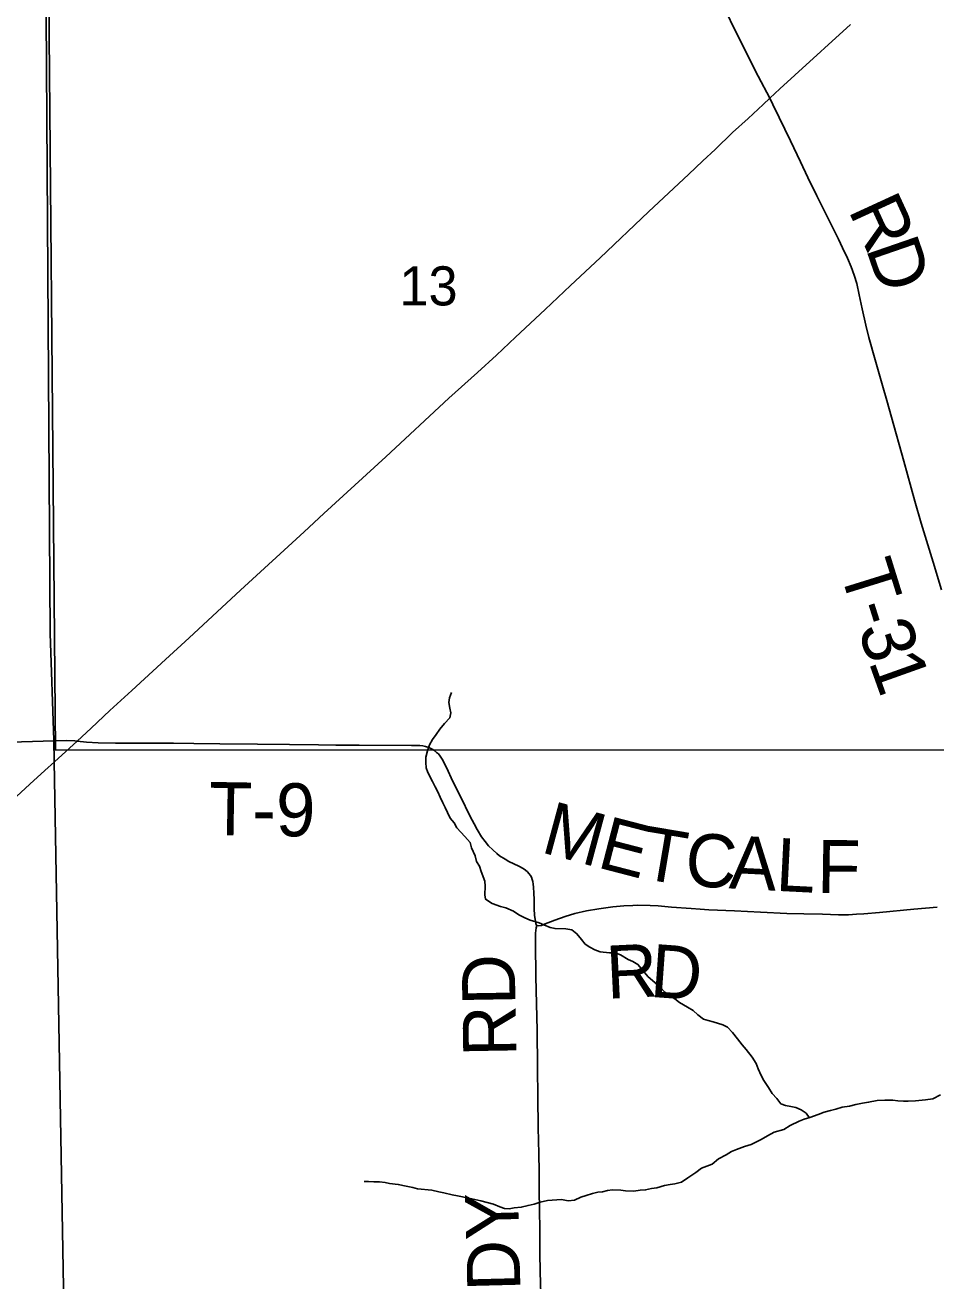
# Model space of a CAD drawing. Extents: x 0 to 34, y 0 to 22.
# Drawn here: x 2.612 to 3.587, y 14.792 to 16.137 of the extents above; entities that cross this region are included whole.
import ezdxf

# ---------------------------------------------------------------- set-up
doc = ezdxf.new("R2010")
doc.units = 0
for name, color, linetype in [('Default', 7, 'Continuous'), ('GM_X_Minor_River', 7, 'Continuous'), ('GM_X_Section', 7, 'Continuous'), ('GM_X_Section_Text', 7, 'Continuous'), ('GM_X_State_Route', 7, 'Continuous'), ('GM_X_Township_Road', 7, 'Continuous'), ('GM_X_Township_Road_Text', 7, 'Continuous'), ('SH_Cut_Line', 7, 'Continuous')]:
    doc.layers.add(name, color=color, linetype=linetype)

msp = doc.modelspace()

# ---------------------------------------------------------------- linework, layer by layer
at = {"layer": 'Default'}
msp.add_lwpolyline([(2.1, 18.375), (2.1, 14.3539), (2.1651, 14.3567), (2.6607, 14.3625), (2.6434, 15.3487), (2.6428, 15.3713), (2.6388, 15.4856), (2.6332, 16.3685), (2.6231, 17.3771), (2.6129, 17.8818), (2.6122, 18.05), (2.6118, 18.3803)], close=True, dxfattribs=at)
msp.add_lwpolyline([(2.6231, 17.3771), (2.6332, 16.3685), (2.6388, 15.4856), (2.6428, 15.3713), (2.6434, 15.3487), (2.6607, 14.3625), (2.7339, 14.3605), (3.1736, 14.3499), (3.5171, 14.3547), (3.6708, 14.3479), (4.282, 14.3483), (4.5209, 14.3512)], dxfattribs=at)
at = {"layer": 'GM_X_Minor_River'}
for points in [[(3.4517, 14.9671), (3.4484, 14.9718), (3.443, 14.9756), (3.4373, 14.9779), (3.4319, 14.979), (3.4262, 14.9801), (3.4213, 14.982), (3.417, 14.9874), (3.4121, 14.9931), (3.4079, 14.9995), (3.4029, 15.0068), (3.4002, 15.0121), (3.3971, 15.0193), (3.3948, 15.025), (3.3906, 15.0319), (3.3841, 15.0399), (3.3799, 15.0452), (3.3749, 15.0513), (3.3696, 15.0581), (3.3642, 15.0638), (3.3592, 15.0665), (3.3489, 15.0695), (3.3436, 15.0711), (3.3386, 15.0726), (3.3325, 15.0772), (3.3275, 15.0817), (3.3214, 15.0855), (3.3126, 15.0905), (3.3076, 15.0943), (3.3019, 15.0977), (3.2969, 15.1015), (3.292, 15.1068), (3.2866, 15.1114), (3.279, 15.1182), (3.274, 15.1243), (3.2683, 15.1312), (3.2629, 15.1342), (3.2579, 15.1365), (3.2495, 15.1415), (3.2438, 15.1434), (3.2377, 15.1437), (3.2278, 15.1445), (3.222, 15.1468), (3.2167, 15.1495), (3.2117, 15.1529), (3.2079, 15.1578), (3.2029, 15.1639), (3.1976, 15.1681), (3.1911, 15.1692), (3.1796, 15.1696), (3.1743, 15.1708), (3.1674, 15.1734), (3.1624, 15.1757), (3.1529, 15.1784), (3.1472, 15.1811), (3.1407, 15.1841), (3.1349, 15.1883), (3.1269, 15.1917), (3.1212, 15.1932), (3.112, 15.1963), (3.1051, 15.2009), (3.1044, 15.2058), (3.1047, 15.2149), (3.1043, 15.2202), (3.1005, 15.2305), (3.0986, 15.2362), (3.0955, 15.2412), (3.094, 15.2476), (3.0901, 15.256), (3.0886, 15.2617), (3.0829, 15.2682), (3.0744, 15.2773), (3.0714, 15.2826), (3.0672, 15.2876), (3.0645, 15.2937), (3.0618, 15.299), (3.0595, 15.3043), (3.0564, 15.3104), (3.0541, 15.3161), (3.0511, 15.3214), (3.0484, 15.3271), (3.0434, 15.3366), (3.0415, 15.3416), (3.0411, 15.3473), (3.0411, 15.353), (3.0429, 15.3598), (3.0452, 15.3663), (3.0483, 15.372), (3.0521, 15.3773), (3.0563, 15.383), (3.0612, 15.3891), (3.0669, 15.3952), (3.068, 15.4005), (3.0669, 15.4054), (3.0657, 15.4115), (3.0665, 15.4165), (3.0688, 15.4222)], [(3.5922, 14.9915), (3.5838, 14.9873), (3.5762, 14.9861), (3.5655, 14.985), (3.5575, 14.9846), (3.5525, 14.9846), (3.5464, 14.985), (3.5411, 14.9858), (3.5327, 14.9858), (3.5243, 14.9854), (3.5151, 14.9835), (3.5086, 14.9824), (3.5014, 14.9812), (3.4949, 14.9793), (3.4869, 14.9782), (3.48, 14.9763), (3.4743, 14.9748), (3.4678, 14.9729), (3.4613, 14.9706), (3.4522, 14.9672), (3.4461, 14.9653)], [(3.4461, 14.9653), (3.4408, 14.9634), (3.4312, 14.9585), (3.4244, 14.9543), (3.4141, 14.9516), (3.4068, 14.9475), (3.4, 14.9437), (3.3893, 14.9383), (3.3824, 14.9361), (3.3737, 14.933), (3.3683, 14.9307), (3.3626, 14.9273), (3.3546, 14.9228), (3.3477, 14.9171), (3.3363, 14.9129), (3.3302, 14.9083), (3.3215, 14.9026), (3.315, 14.8981), (3.3077, 14.8962), (3.3028, 14.8954), (3.2967, 14.8943), (3.2883, 14.892), (3.2829, 14.8912), (3.2765, 14.8897), (3.2707, 14.8893), (3.2639, 14.8882), (3.2551, 14.8886), (3.2501, 14.8894), (3.241, 14.8897), (3.2356, 14.889), (3.2303, 14.8878), (3.2253, 14.8871), (3.2196, 14.886), (3.2127, 14.8837), (3.207, 14.8818), (3.2002, 14.8787), (3.1937, 14.878), (3.1864, 14.8795), (3.1715, 14.8784), (3.1635, 14.8765), (3.157, 14.8746), (3.1506, 14.8731), (3.1433, 14.8712), (3.1357, 14.8704), (3.1303, 14.8696), (3.1254, 14.8697), (3.1204, 14.8716), (3.1135, 14.8746), (3.1002, 14.878), (3.0872, 14.8807), (3.075, 14.8834), (3.0692, 14.8845), (3.0605, 14.8864), (3.0551, 14.8876), (3.0475, 14.8895), (3.0322, 14.891), (3.0272, 14.8921), (3.02, 14.8937), (3.0116, 14.8956), (3.0024, 14.8967), (2.9975, 14.8975), (2.9914, 14.8982), (2.9856, 14.8982), (2.9799, 14.8986), (2.975, 14.8986)]]:
    msp.add_lwpolyline(points, dxfattribs=at)
at = {"layer": 'GM_X_Section'}
msp.add_lwpolyline([(2.6357, 16.367), (3.1951, 16.3831), (3.3278, 16.3702), (3.6522, 16.3668), (3.6534, 16.349), (3.6643, 15.3607), (2.6446, 15.3609)], close=True, dxfattribs=at)
at = {"layer": 'GM_X_State_Route'}
for points in [[(2.6436, 15.3481), (2.6677, 15.3702), (2.6828, 15.3841), (2.7029, 15.4031), (2.7263, 15.4244), (2.7626, 15.4578), (2.7879, 15.4809), (2.8428, 15.5319), (2.9108, 15.5944), (2.9319, 15.614), (2.9983, 15.6748), (3.0659, 15.7374), (3.0963, 15.7651), (3.1168, 15.7836), (3.1372, 15.8028), (3.1689, 15.8326), (3.196, 15.8581), (3.2278, 15.8878), (3.2797, 15.9369), (3.3067, 15.9625), (3.3225, 15.977), (3.3378, 15.9917), (3.3509, 16.0039), (3.3696, 16.0219), (3.3861, 16.0371), (3.4023, 16.0521), (3.4093, 16.0586), (3.4202, 16.0686), (3.4362, 16.0833), (3.4959, 16.1377)], [(2.1, 14.819), (2.1251, 14.8471), (2.1408, 14.8645), (2.1583, 14.8839), (2.179, 14.907), (2.1997, 14.9302), (2.2353, 14.9691), (2.2482, 14.9825), (2.2682, 15.002), (2.291, 15.023), (2.3069, 15.0378), (2.3275, 15.0567), (2.4005, 15.124), (2.4301, 15.1514), (2.5189, 15.2336), (2.5599, 15.2716), (2.617, 15.3242), (2.6331, 15.3388), (2.6436, 15.3481)]]:
    msp.add_lwpolyline(points, dxfattribs=at)
at = {"layer": 'GM_X_Township_Road'}
for points in [[(3.4093, 16.0586), (3.3971, 16.0824), (3.3803, 16.1156), (3.354, 16.1685), (3.3365, 16.2049), (3.3195, 16.2415), (3.3069, 16.2699), (3.2898, 16.3099), (3.2723, 16.3531), (3.2668, 16.3676), (3.264, 16.3765), (3.2633, 16.379)], [(3.5933, 15.5323), (3.5842, 15.562), (3.5714, 15.6035), (3.5648, 15.6272), (3.5528, 15.6702), (3.5396, 15.7171), (3.5347, 15.7351), (3.5301, 15.7509), (3.5224, 15.7786), (3.5155, 15.8025), (3.5121, 15.8156), (3.5084, 15.833), (3.5051, 15.8483), (3.5025, 15.8604), (3.4998, 15.8692), (3.4967, 15.8781), (3.4925, 15.8873), (3.4874, 15.8986), (3.4828, 15.9078), (3.4709, 15.932), (3.4599, 15.9543), (3.4503, 15.9738), (3.4423, 15.9906), (3.4315, 16.0129), (3.4195, 16.038), (3.4127, 16.052), (3.4093, 16.0586)], [(2.1, 15.3565), (2.1347, 15.3575), (2.1565, 15.3582), (2.1938, 15.359), (2.2405, 15.3602), (2.2809, 15.3614), (2.3182, 15.3623), (2.3586, 15.3633), (2.4177, 15.3648), (2.4581, 15.3659), (2.4891, 15.3664), (2.5202, 15.3673), (2.5482, 15.3682), (2.5855, 15.3689), (2.643, 15.3707)], [(2.643, 15.3707), (2.6563, 15.3709), (2.6655, 15.3705), (2.6677, 15.3702)], [(2.6677, 15.3702), (2.6778, 15.3692), (2.6902, 15.3683), (2.7089, 15.368), (2.7461, 15.3679), (2.771, 15.3679), (2.7927, 15.3677), (2.8207, 15.3673), (2.8611, 15.3669), (2.8953, 15.3667), (2.9263, 15.3662), (2.9449, 15.3661), (2.9698, 15.366), (3.0257, 15.3657), (3.0349, 15.3654), (3.0379, 15.3651), (3.0409, 15.3644), (3.0442, 15.3635), (3.0466, 15.3624), (3.0487, 15.3612), (3.0508, 15.3598), (3.0526, 15.3582), (3.0546, 15.3565), (3.0566, 15.354), (3.0587, 15.3509), (3.0633, 15.342), (3.0702, 15.327), (3.0782, 15.3108), (3.0886, 15.2895), (3.0928, 15.2816), (3.0961, 15.2756), (3.1009, 15.2679), (3.1045, 15.2629), (3.1083, 15.2582), (3.1128, 15.2538), (3.1171, 15.2499), (3.1201, 15.2476), (3.126, 15.2437), (3.1301, 15.2414), (3.1406, 15.2362), (3.1455, 15.2337), (3.148, 15.2319), (3.1499, 15.2303), (3.1516, 15.2284), (3.1531, 15.2264), (3.1542, 15.2244), (3.1551, 15.222), (3.1557, 15.2198), (3.1562, 15.2171), (3.1565, 15.2137), (3.1568, 15.2076), (3.157, 15.2005), (3.1572, 15.1912), (3.1576, 15.1835), (3.1584, 15.1773), (3.159, 15.1746), (3.1601, 15.1729)], [(3.1601, 15.1729), (3.1623, 15.1725), (3.165, 15.1729), (3.1673, 15.174), (3.1793, 15.1785), (3.1903, 15.1826), (3.2007, 15.1856), (3.2131, 15.1885), (3.2264, 15.1907), (3.2413, 15.1927), (3.2532, 15.1938), (3.2629, 15.1944), (3.268, 15.1946), (3.2815, 15.1943), (3.2899, 15.1938), (3.3043, 15.1926), (3.3254, 15.1909), (3.3347, 15.1903), (3.344, 15.1897), (3.3718, 15.1886), (3.3996, 15.1871), (3.4275, 15.1858), (3.4457, 15.1854), (3.466, 15.1848), (3.4829, 15.1843), (3.4891, 15.1843), (3.4936, 15.1844), (3.5023, 15.1848), (3.5101, 15.1854), (3.5267, 15.1868), (3.5638, 15.1902), (3.5885, 15.1925)], [(3.1642, 14.7779), (3.1637, 14.802), (3.1633, 14.8223), (3.1631, 14.8468), (3.1627, 14.8684), (3.1626, 14.8894), (3.1625, 14.9085), (3.1621, 14.9293), (3.1618, 14.9417), (3.1615, 14.9572), (3.1612, 14.9883), (3.1608, 15.021), (3.1602, 15.0607), (3.1597, 15.089), (3.1589, 15.1182), (3.1585, 15.1537), (3.1585, 15.1647), (3.1589, 15.1675), (3.1594, 15.1703), (3.1601, 15.1729)]]:
    msp.add_lwpolyline(points, dxfattribs=at)
at = {"layer": 'SH_Cut_Line'}
msp.add_lwpolyline([(2.6032, 20.9), (2.1, 20.9), (2.1, 14.3539), (2.1651, 14.3567), (2.6607, 14.3625), (2.6434, 15.3487), (2.6428, 15.3713), (2.6388, 15.4856), (2.6332, 16.3685), (2.6231, 17.3771), (2.6129, 17.8818), (2.6122, 18.05), (2.6118, 18.3803), (2.6161, 18.3799), (2.6204, 18.3797), (2.6263, 18.3795), (2.6292, 18.3794), (2.6281, 18.8843), (2.6224, 19.9515), (2.6032, 20.8721)], close=True, dxfattribs=at)
msp.add_lwpolyline([(2.6231, 17.3771), (2.6332, 16.3685), (2.6388, 15.4856), (2.6428, 15.3713), (2.6434, 15.3487), (2.6607, 14.3625), (2.7339, 14.3605), (3.1736, 14.3499), (3.5171, 14.3547), (3.6708, 14.3479), (4.282, 14.3483), (4.5209, 14.3512)], dxfattribs=at)

# ---------------------------------------------------------------- texts
at = {"layer": 'GM_X_Section_Text'}
msp.add_text('13', height=0.04186, rotation=0, dxfattribs=at).set_placement((3.0129, 15.8368))
at = {"layer": 'GM_X_Township_Road_Text'}
for s, height, rotation, p in [('R', 0.0568, 294.7119, (3.4929, 15.9391)), ('D', 0.0568, 289.0392, (3.5119, 15.8981)), ('T', 0.0568, 287.2904, (3.4837, 15.5541)), ('-', 0.0568, 287.391, (3.4964, 15.5134)), ('3', 0.0568, 287.8064, (3.5035, 15.4907)), ('1', 0.0568, 289.6429, (3.5149, 15.4555)), ('T-9', 0.05682, 359.0521, (2.8085, 15.2698)), ('M', 0.0568, 344.8662, (3.1629, 15.2516)), ('E', 0.0568, 345.4542, (3.2231, 15.2354)), ('T', 0.0568, 350.3565, (3.2694, 15.2236)), ('C', 0.0568, 356.2413, (3.3176, 15.2157)), ('A', 0.0568, 357.0614, (3.3651, 15.2126)), ('L', 0.0568, 357.1059, (3.415, 15.21)), ('F', 0.0568, 359.2814, (3.4598, 15.2078)), ('R', 0.0568, 2.7507, (3.2355, 15.0943)), ('D', 0.0568, 355.9166, (3.2803, 15.0965)), ('RD', 0.05682, 90.993, (3.1381, 15.0329)), ('SNODDY', 0.05682, 91.4671, (3.1481, 14.5625))]:
    msp.add_text(s, height=height, rotation=rotation, dxfattribs=at).set_placement(p)

doc.saveas('drawing.dxf')
